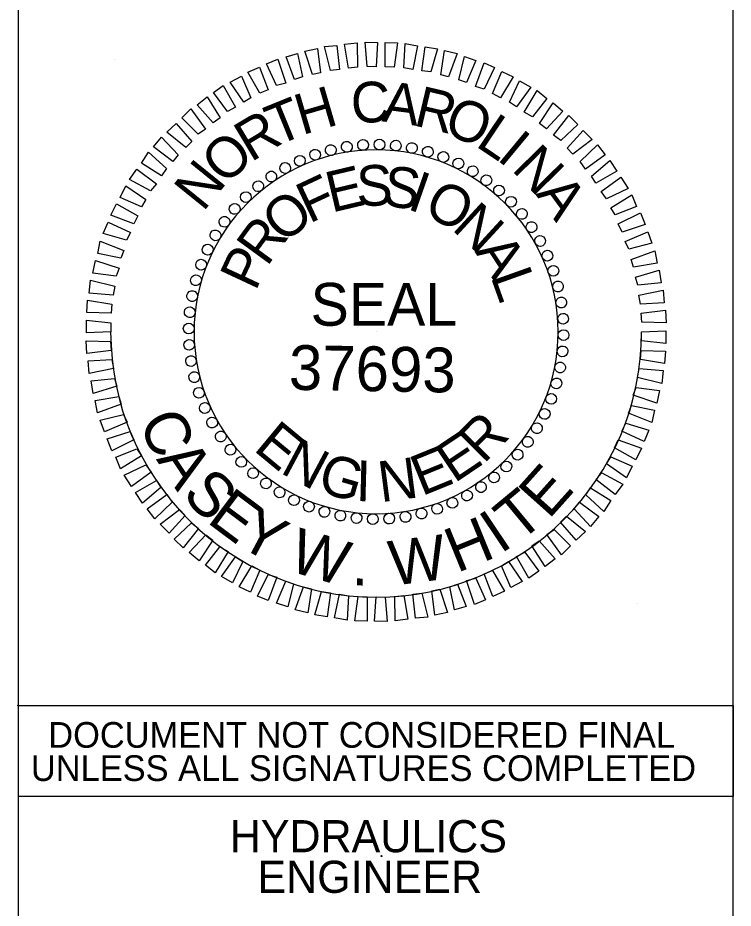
# Model space of a CAD drawing. Extents: x 2.6 to 3.27, y 0.03 to 1.77.
# Drawn here: x 2.604 to 2.7708, y 1.3512 to 1.5591 of the extents above; entities that cross this region are included whole.
import ezdxf

# ---------------------------------------------------------------- set-up
doc = ezdxf.new("R2010")
doc.units = 0
for name, color, linetype in [('Draft_RDY_Construction_Class_Element', 7, 'Continuous'), ('Scratch_Level_2', 7, 'Continuous'), ('Sheet_PE_Note_CELL', 7, 'Continuous'), ('Sheet_Plan_CELL', 7, 'Continuous'), ('Sheet_Sticker_Incomplete_CELL', 7, 'Continuous')]:
    doc.layers.add(name, color=color, linetype=linetype)

msp = doc.modelspace()

# ---------------------------------------------------------------- linework, layer by layer
at = {"layer": 'Draft_RDY_Construction_Class_Element'}
for p, q in [((2.60416, 0.0625), (2.60416, 1.77083)), ((2.77078, 1.77083), (2.77078, 0.0625))]:
    msp.add_line(p, q, dxfattribs=at)
at = {"layer": 'Scratch_Level_2'}
for p, q in [((2.62662, 1.54928), (2.62662, 1.54928)), ((2.68756, 1.48578), (2.68756, 1.48578)), ((2.7485, 1.42228), (2.7485, 1.42228))]:
    msp.add_line(p, q, dxfattribs=at)
for radius, start, end in [(0.04247, 0, 180), (0.06193, 180, 0), (0.04247, 180, 0)]:
    msp.add_arc((2.68756, 1.48578), radius, start, end, dxfattribs=at)
at = {"layer": 'Sheet_PE_Note_CELL'}
for p, q in [((2.67692, 1.52823), (2.67692, 1.52823)), ((2.68076, 1.52893), (2.68076, 1.52893)), ((2.68451, 1.52945), (2.68451, 1.52945)), ((2.68834, 1.52954), (2.68834, 1.52954)), ((2.69218, 1.52928), (2.69218, 1.52928)), ((2.69593, 1.52867), (2.69593, 1.52867)), ((2.67326, 1.52719), (2.67326, 1.52719)), ((2.69959, 1.52788), (2.69959, 1.52788)), ((2.70325, 1.52666), (2.70325, 1.52666)), ((2.66637, 1.52405), (2.66637, 1.52405)), ((2.66977, 1.52579), (2.66977, 1.52579)), ((2.70674, 1.52509), (2.70674, 1.52509)), ((2.66306, 1.52204), (2.66306, 1.52204)), ((2.71013, 1.52335), (2.71013, 1.52335)), ((2.66001, 1.51986), (2.66001, 1.51986)), ((2.71327, 1.52117), (2.71327, 1.52117)), ((2.71632, 1.51882), (2.71632, 1.51882)), ((2.65713, 1.51725), (2.65713, 1.51725)), ((2.71903, 1.5162), (2.71903, 1.5162)), ((2.65452, 1.51455), (2.65452, 1.51455)), ((2.65217, 1.51149), (2.65217, 1.51149)), ((2.72164, 1.51332), (2.72164, 1.51332)), ((2.72382, 1.51027), (2.72382, 1.51027)), ((2.64999, 1.50836), (2.64999, 1.50836)), ((2.72583, 1.50696), (2.72583, 1.50696)), ((2.64824, 1.50496), (2.64824, 1.50496)), ((2.72757, 1.50356), (2.72757, 1.50356)), ((2.64667, 1.50147), (2.64667, 1.50147)), ((2.72896, 1.50007), (2.72896, 1.50007)), ((2.64545, 1.49781), (2.64545, 1.49781)), ((2.73001, 1.49641), (2.73001, 1.49641)), ((2.64467, 1.49415), (2.64467, 1.49415)), ((2.73071, 1.49258), (2.73071, 1.49258)), ((2.64406, 1.4904), (2.64406, 1.4904)), ((2.73123, 1.48883), (2.73123, 1.48883)), ((2.6438, 1.48656), (2.6438, 1.48656)), ((2.73132, 1.48499), (2.73132, 1.48499)), ((2.64388, 1.48273), (2.64388, 1.48273)), ((2.73106, 1.48116), (2.73106, 1.48116)), ((2.64441, 1.47898), (2.64441, 1.47898)), ((2.73045, 1.47741), (2.73045, 1.47741)), ((2.6451, 1.47514), (2.6451, 1.47514)), ((2.72966, 1.47375), (2.72966, 1.47375)), ((2.64615, 1.47148), (2.64615, 1.47148)), ((2.72844, 1.47009), (2.72844, 1.47009)), ((2.64755, 1.468), (2.64755, 1.468)), ((2.72687, 1.4666), (2.72687, 1.4666)), ((2.64929, 1.4646), (2.64929, 1.4646)), ((2.72513, 1.4632), (2.72513, 1.4632)), ((2.65129, 1.46128), (2.65129, 1.46128)), ((2.72295, 1.46006), (2.72295, 1.46006)), ((2.65347, 1.45823), (2.65347, 1.45823)), ((2.65609, 1.45536), (2.65609, 1.45536)), ((2.7206, 1.45701), (2.7206, 1.45701)), ((2.71798, 1.45431), (2.71798, 1.45431)), ((2.65879, 1.45274), (2.65879, 1.45274)), ((2.7151, 1.45169), (2.7151, 1.45169)), ((2.66184, 1.45039), (2.66184, 1.45039)), ((2.71205, 1.44951), (2.71205, 1.44951)), ((2.66498, 1.44821), (2.66498, 1.44821)), ((2.70874, 1.44751), (2.70874, 1.44751)), ((2.66838, 1.44646), (2.66838, 1.44646)), ((2.67187, 1.44489), (2.67187, 1.44489)), ((2.70534, 1.44577), (2.70534, 1.44577)), ((2.67553, 1.44367), (2.67553, 1.44367)), ((2.67919, 1.44289), (2.67919, 1.44289)), ((2.69819, 1.44333), (2.69819, 1.44333)), ((2.70185, 1.44437), (2.70185, 1.44437)), ((2.68294, 1.44228), (2.68294, 1.44228)), ((2.68677, 1.44202), (2.68677, 1.44202)), ((2.69061, 1.44211), (2.69061, 1.44211)), ((2.69436, 1.44263), (2.69436, 1.44263))]:
    msp.add_line(p, q, dxfattribs=at)
for points in [[(2.68111, 1.54732), (2.68015, 1.5529), (2.68311, 1.55325), (2.6832, 1.54758)], [(2.68547, 1.54776), (2.68503, 1.55342), (2.68791, 1.55334), (2.68756, 1.54767)], [(2.68965, 1.54767), (2.68965, 1.55334), (2.69253, 1.55325), (2.69174, 1.54758)], [(2.69401, 1.54741), (2.69436, 1.55308), (2.69723, 1.55255), (2.6961, 1.54706)], [(2.67274, 1.54584), (2.67091, 1.55133), (2.67387, 1.55194), (2.67457, 1.54628)], [(2.67692, 1.5468), (2.67553, 1.55238), (2.6784, 1.55264), (2.67901, 1.54706)], [(2.69819, 1.54671), (2.69898, 1.55229), (2.70185, 1.55185), (2.70028, 1.54645)], [(2.70264, 1.54575), (2.70351, 1.55142), (2.70647, 1.55072), (2.70447, 1.54532)], [(2.66428, 1.54331), (2.66202, 1.54837), (2.66463, 1.54941), (2.66646, 1.54383)], [(2.66855, 1.54471), (2.66655, 1.54994), (2.66925, 1.55072), (2.67038, 1.54532)], [(2.70682, 1.54462), (2.70813, 1.55002), (2.71083, 1.54915), (2.70865, 1.54401)], [(2.66045, 1.54148), (2.65766, 1.54636), (2.66036, 1.54758), (2.66236, 1.54227)], [(2.71074, 1.54305), (2.71275, 1.54854), (2.71519, 1.5475), (2.71275, 1.54244)], [(2.6567, 1.53939), (2.65347, 1.5441), (2.65618, 1.54549), (2.65835, 1.54044)], [(2.71467, 1.54139), (2.71685, 1.54654), (2.71955, 1.54532), (2.71659, 1.54044)], [(2.65286, 1.53721), (2.64964, 1.54166), (2.6519, 1.54331), (2.65478, 1.53826)], [(2.71868, 1.53939), (2.72103, 1.54436), (2.72365, 1.54288), (2.72033, 1.53834)], [(2.64955, 1.53459), (2.6458, 1.53878), (2.64816, 1.54061), (2.65121, 1.53573)], [(2.72208, 1.53704), (2.72513, 1.54209), (2.72739, 1.54026), (2.724, 1.53599)], [(2.72565, 1.53442), (2.72888, 1.53921), (2.73114, 1.5373), (2.72731, 1.5332)], [(2.64606, 1.53189), (2.64223, 1.53573), (2.64432, 1.53782), (2.64772, 1.53311)], [(2.72896, 1.53172), (2.73254, 1.53625), (2.73463, 1.53416), (2.73062, 1.53041)], [(2.64319, 1.52884), (2.63874, 1.53242), (2.64092, 1.53442), (2.64458, 1.53024)], [(2.7321, 1.52867), (2.73585, 1.53276), (2.73794, 1.53067), (2.73341, 1.52727)], [(2.64014, 1.52553), (2.6356, 1.52893), (2.63752, 1.53119), (2.64136, 1.5271)], [(2.73515, 1.52553), (2.73916, 1.52945), (2.74099, 1.5271), (2.73637, 1.52379)], [(2.63752, 1.52222), (2.63281, 1.52518), (2.63447, 1.52771), (2.63865, 1.52387)], [(2.63491, 1.51873), (2.63002, 1.52134), (2.63177, 1.52379), (2.6363, 1.5203)], [(2.73777, 1.52213), (2.74204, 1.52579), (2.7437, 1.52326), (2.73881, 1.52047)], [(2.74003, 1.51856), (2.74465, 1.52187), (2.74631, 1.51925), (2.74126, 1.51681)], [(2.63281, 1.51498), (2.62784, 1.51716), (2.62915, 1.51986), (2.63386, 1.51664)], [(2.7423, 1.51472), (2.74718, 1.51777), (2.74832, 1.51507), (2.74335, 1.51306)], [(2.63107, 1.51097), (2.62567, 1.51298), (2.62697, 1.51568), (2.63194, 1.51289)], [(2.74404, 1.51097), (2.74919, 1.51359), (2.75032, 1.5108), (2.74492, 1.50905)], [(2.62933, 1.50714), (2.62392, 1.5087), (2.62505, 1.51141), (2.63029, 1.50897)], [(2.74561, 1.50687), (2.75093, 1.50914), (2.75189, 1.50644), (2.74649, 1.50504)], [(2.62802, 1.50295), (2.62261, 1.50408), (2.62322, 1.50696), (2.62872, 1.50478)], [(2.74701, 1.50269), (2.75259, 1.50469), (2.75311, 1.50182), (2.74762, 1.50086)], [(2.62689, 1.49877), (2.62148, 1.49946), (2.62209, 1.50243), (2.62758, 1.5006)], [(2.74805, 1.49851), (2.75355, 1.50016), (2.75407, 1.4972), (2.74858, 1.49667)], [(2.62619, 1.49432), (2.62061, 1.49484), (2.62096, 1.49781), (2.62662, 1.49641)], [(2.74884, 1.49432), (2.75451, 1.49554), (2.75477, 1.49258), (2.74919, 1.49223)], [(2.62575, 1.49014), (2.62009, 1.49031), (2.62026, 1.49319), (2.62593, 1.49223)], [(2.74936, 1.49014), (2.75503, 1.49083), (2.7552, 1.48787), (2.74954, 1.48804)], [(2.62567, 1.48578), (2.62, 1.48552), (2.62, 1.48848), (2.62567, 1.48787)], [(2.74945, 1.48578), (2.75512, 1.48604), (2.75512, 1.48308), (2.74945, 1.48369)], [(2.62575, 1.48142), (2.62009, 1.48072), (2.61991, 1.48369), (2.62558, 1.48351)], [(2.74936, 1.48142), (2.75503, 1.48125), (2.75485, 1.47837), (2.74919, 1.47933)], [(2.62628, 1.47724), (2.62061, 1.47602), (2.62035, 1.47898), (2.62593, 1.47933)], [(2.74893, 1.47724), (2.75451, 1.47671), (2.75416, 1.47375), (2.74849, 1.47514)], [(2.62706, 1.47305), (2.62157, 1.4714), (2.62105, 1.47436), (2.62654, 1.47488)], [(2.74823, 1.47279), (2.75363, 1.47209), (2.75302, 1.46913), (2.74753, 1.47096)], [(2.62811, 1.46887), (2.62253, 1.46686), (2.622, 1.46974), (2.6275, 1.4707)], [(2.7471, 1.46861), (2.7525, 1.46747), (2.75189, 1.4646), (2.7464, 1.46677)], [(2.6295, 1.46468), (2.62418, 1.46242), (2.62322, 1.46512), (2.62863, 1.46651)], [(2.74579, 1.46442), (2.75119, 1.46285), (2.75006, 1.46015), (2.74483, 1.46259)], [(2.63107, 1.46059), (2.62593, 1.45797), (2.62479, 1.46076), (2.6302, 1.4625)], [(2.74404, 1.46059), (2.74945, 1.45858), (2.74814, 1.45588), (2.74317, 1.45867)], [(2.63281, 1.45684), (2.62793, 1.45379), (2.6268, 1.45649), (2.63177, 1.45849)], [(2.7423, 1.45658), (2.74727, 1.4544), (2.74596, 1.45169), (2.74126, 1.45492)], [(2.63508, 1.453), (2.63046, 1.44969), (2.6288, 1.4523), (2.63386, 1.45475)], [(2.63735, 1.44943), (2.63307, 1.44577), (2.63142, 1.44829), (2.6363, 1.45108)], [(2.74021, 1.45283), (2.74509, 1.45021), (2.74335, 1.44777), (2.73881, 1.45126)], [(2.73759, 1.44934), (2.7423, 1.44638), (2.74064, 1.44385), (2.73646, 1.44768)], [(2.63996, 1.44603), (2.63595, 1.44211), (2.63412, 1.44446), (2.63874, 1.44777)], [(2.73498, 1.44603), (2.73951, 1.44263), (2.73759, 1.44036), (2.73376, 1.44446)], [(2.64301, 1.44289), (2.63926, 1.43879), (2.63717, 1.44088), (2.6417, 1.44428)], [(2.73193, 1.44272), (2.73637, 1.43914), (2.73419, 1.43714), (2.73053, 1.44132)], [(2.64615, 1.43984), (2.64258, 1.43531), (2.64048, 1.4374), (2.64449, 1.44115)], [(2.72905, 1.43966), (2.73289, 1.43583), (2.73079, 1.43374), (2.72739, 1.43844)], [(2.64946, 1.43714), (2.64624, 1.43234), (2.64397, 1.43426), (2.64781, 1.43836)], [(2.72556, 1.43696), (2.72931, 1.43278), (2.72696, 1.43095), (2.72391, 1.43583)], [(2.65304, 1.43452), (2.64999, 1.42947), (2.64772, 1.4313), (2.65112, 1.43557)], [(2.65644, 1.43217), (2.65408, 1.4272), (2.65147, 1.42868), (2.65478, 1.43321)], [(2.72225, 1.43435), (2.72548, 1.4299), (2.72321, 1.42824), (2.72033, 1.4333)], [(2.66045, 1.43016), (2.65827, 1.42502), (2.65557, 1.42624), (2.65853, 1.43112)], [(2.71842, 1.43217), (2.72164, 1.42746), (2.71894, 1.42607), (2.71676, 1.43112)], [(2.66437, 1.42851), (2.66236, 1.42301), (2.65992, 1.42406), (2.66236, 1.42912)], [(2.71083, 1.42824), (2.7131, 1.42319), (2.71048, 1.42214), (2.70865, 1.42772)], [(2.71467, 1.43008), (2.71746, 1.42519), (2.71475, 1.42397), (2.71275, 1.42929)], [(2.66829, 1.42694), (2.66698, 1.42153), (2.66428, 1.4224), (2.66646, 1.42755)], [(2.67248, 1.4258), (2.6716, 1.42014), (2.66864, 1.42084), (2.67065, 1.42624)], [(2.70656, 1.42685), (2.70857, 1.42162), (2.70586, 1.42084), (2.70473, 1.42624)], [(2.67692, 1.42485), (2.67614, 1.41927), (2.67326, 1.4197), (2.67483, 1.42511)], [(2.68111, 1.42415), (2.68076, 1.41848), (2.67788, 1.419), (2.67901, 1.4245)], [(2.69401, 1.42424), (2.69497, 1.41866), (2.692, 1.41831), (2.69192, 1.42397)], [(2.69819, 1.42476), (2.69959, 1.41918), (2.69671, 1.41892), (2.6961, 1.4245)], [(2.70238, 1.42572), (2.70421, 1.42023), (2.70124, 1.41961), (2.70055, 1.42528)], [(2.68547, 1.42389), (2.68547, 1.41822), (2.68259, 1.41831), (2.68337, 1.42397)], [(2.68965, 1.4238), (2.69009, 1.41813), (2.68721, 1.41822), (2.68756, 1.42389)]]:
    msp.add_lwpolyline(points, close=True, dxfattribs=at)
for centre, major_axis in [((2.68072, 1.52897), (-0.0002, 0.00124)), ((2.68451, 1.5294), (-0.00009, 0.00125)), ((2.68832, 1.5295), (0.00002, 0.00126)), ((2.69213, 1.52926), (0.00013, 0.00125)), ((2.6959, 1.5287), (0.00024, 0.00123)), ((2.67332, 1.52712), (-0.00041, 0.00119)), ((2.67698, 1.5282), (-0.0003, 0.00122)), ((2.69961, 1.52781), (0.00035, 0.00121)), ((2.70323, 1.5266), (0.00045, 0.00117)), ((2.66977, 1.52572), (-0.00051, 0.00115)), ((2.70673, 1.52508), (0.00055, 0.00113)), ((2.66636, 1.52402), (-0.00061, 0.0011)), ((2.71008, 1.52326), (0.00065, 0.00108)), ((2.66311, 1.52203), (-0.0007, 0.00104)), ((2.71326, 1.52115), (0.00074, 0.00102)), ((2.66004, 1.51976), (-0.00079, 0.000976)), ((2.71624, 1.51878), (0.000824, 0.000947)), ((2.65718, 1.51723), (-0.000872, 0.000903)), ((2.71901, 1.51615), (0.000903, 0.000872)), ((2.65456, 1.51446), (-0.000947, 0.000824)), ((2.72154, 1.5133), (0.000976, 0.00079)), ((2.65218, 1.51148), (-0.00102, 0.00074)), ((2.72381, 1.51023), (0.00104, 0.0007)), ((2.65008, 1.5083), (-0.00108, 0.00065)), ((2.7258, 1.50698), (0.0011, 0.00061)), ((2.64826, 1.50495), (-0.00113, 0.00055)), ((2.7275, 1.50356), (0.00115, 0.00051)), ((2.64674, 1.50145), (-0.00117, 0.00045)), ((2.7289, 1.50001), (0.00119, 0.00041)), ((2.64553, 1.49783), (-0.00121, 0.00035)), ((2.72998, 1.49636), (0.00122, 0.0003)), ((2.64464, 1.49412), (-0.00123, 0.00024)), ((2.73074, 1.49262), (0.00124, 0.0002)), ((2.64407, 1.49035), (-0.00125, 0.00013)), ((2.73118, 1.48883), (0.00125, 0.00009)), ((2.64384, 1.48654), (-0.00126, 0.00002)), ((2.73128, 1.48502), (0.00126, -0.00002)), ((2.64394, 1.48273), (-0.00125, -0.00009)), ((2.73104, 1.48121), (0.00125, -0.00013)), ((2.64437, 1.47894), (-0.00124, -0.0002)), ((2.73048, 1.47744), (0.00123, -0.00024)), ((2.64513, 1.4752), (-0.00122, -0.0003)), ((2.72959, 1.47373), (0.00121, -0.00035)), ((2.64621, 1.47154), (-0.00119, -0.00041)), ((2.72838, 1.47011), (0.00117, -0.00045)), ((2.64761, 1.46799), (-0.00115, -0.00051)), ((2.72686, 1.46661), (0.00113, -0.00055)), ((2.64931, 1.46458), (-0.0011, -0.00061)), ((2.72504, 1.46326), (0.00108, -0.00065)), ((2.65131, 1.46133), (-0.00104, -0.0007)), ((2.72293, 1.46008), (0.00102, -0.00074)), ((2.65358, 1.45826), (-0.000976, -0.00079)), ((2.72056, 1.45709), (0.000947, -0.000824)), ((2.6561, 1.4554), (-0.000903, -0.000872)), ((2.71793, 1.45432), (0.000872, -0.000903)), ((2.65887, 1.45278), (-0.000824, -0.000947)), ((2.71507, 1.4518), (0.00079, -0.000976)), ((2.66186, 1.4504), (-0.00074, -0.00102)), ((2.66504, 1.4483), (-0.00065, -0.00108)), ((2.70876, 1.44754), (0.00061, -0.0011)), ((2.71201, 1.44953), (0.0007, -0.00104)), ((2.66839, 1.44648), (-0.00055, -0.00113)), ((2.70534, 1.44583), (0.00051, -0.00115)), ((2.67189, 1.44496), (-0.00045, -0.00117)), ((2.6755, 1.44375), (-0.00035, -0.00121)), ((2.70179, 1.44444), (0.00041, -0.00119)), ((2.67921, 1.44286), (-0.00024, -0.00123)), ((2.68299, 1.44229), (-0.00013, -0.00125)), ((2.68679, 1.44206), (-0.00002, -0.00126)), ((2.69061, 1.44216), (0.00009, -0.00125)), ((2.6944, 1.44259), (0.0002, -0.00124)), ((2.69814, 1.44335), (0.0003, -0.00122))]:
    msp.add_ellipse(centre, major_axis=major_axis, ratio=0.999708, dxfattribs=at)
at = {"layer": 'Sheet_Plan_CELL'}
msp.add_line((2.77084, 1.37732), (2.60417, 1.37732), dxfattribs=at)
for centre in [(2.68745, 1.4923), (2.60407, 1.39855), (2.68878, 1.36338)]:
    msp.add_circle(centre, 0.0001, dxfattribs=at)
at = {"layer": 'Sheet_Sticker_Incomplete_CELL'}
msp.add_lwpolyline([(2.60417, 1.39855), (2.77084, 1.39855), (2.77084, 1.37732), (2.60417, 1.37732)], close=True, dxfattribs=at)

# ---------------------------------------------------------------- texts
at = {"layer": 'Sheet_PE_Note_CELL'}
for s, height, rotation, p in [('H', 0.0095, 16.2881, (2.67028, 1.53167)), ('C', 0.0095, 1.4832, (2.68176, 1.53454)), ('A', 0.0095, 352.5864, (2.68873, 1.53494)), ('R', 0.0095, 346.666, (2.69605, 1.53402)), ('T', 0.0095, 22.179, (2.66429, 1.5291)), ('O', 0.0095, 337.821, (2.70288, 1.53234)), ('R', 0.0095, 30.9582, (2.65834, 1.52528)), ('L', 0.0095, 326.1343, (2.71049, 1.52928)), ('I', 0.0095, 320.353, (2.71547, 1.52615)), ('O', 0.0095, 42.5191, (2.65228, 1.51978)), ('N', 0.0095, 314.6222, (2.71894, 1.5236)), ('N', 0.0095, 51.0517, (2.64718, 1.51361)), ('E', 0.0095, 13.334, (2.67715, 1.51357)), ('S', 0.0095, 1.4832, (2.68303, 1.51511)), ('S', 0.0095, 352.5864, (2.68881, 1.5153)), ('F', 0.0095, 25.1139, (2.67196, 1.51098)), ('I', 0.0095, 340.7633, (2.69454, 1.51452)), ('O', 0.0095, 331.9594, (2.69823, 1.51345)), ('A', 0.0095, 306.1346, (2.72462, 1.51794)), ('O', 0.0095, 39.647, (2.66597, 1.50612)), ('N', 0.0095, 317.4809, (2.70499, 1.50974)), ('R', 0.0095, 53.8654, (2.66207, 1.5008)), ('P', 0.0095, 64.9491, (2.6594, 1.49507)), ('A', 0.0095, 303.3373, (2.71045, 1.50454)), ('L', 0.0095, 289.6205, (2.7142, 1.49873)), ('37693', 0.010461, 359, (2.66714, 1.47226)), ('C', 0.01046, 295.0509, (2.63198, 1.46464)), ('R', 0.0095, 45.3778, (2.71262, 1.45479)), ('E', 0.0095, 320.353, (2.6587, 1.45825)), ('E', 0.0095, 33.8657, (2.70579, 1.45032)), ('N', 0.0095, 331.9594, (2.66492, 1.45296)), ('A', 0.01046, 303.3373, (2.63615, 1.45602)), ('E', 0.0095, 22.179, (2.69819, 1.44734)), ('G', 0.0095, 343.7119, (2.67351, 1.44862)), ('I', 0.0095, 358.5168, (2.68271, 1.44628)), ('N', 0.0095, 7.4136, (2.68863, 1.44598)), ('S', 0.01046, 314.6222, (2.64201, 1.44751)), ('E', 0.01046, 48.2222, (2.7278, 1.44181)), ('E', 0.01046, 323.2378, (2.64781, 1.44145)), ('T', 0.01046, 39.647, (2.72084, 1.43634)), ('Y', 0.01046, 331.9594, (2.65481, 1.43603)), ('I', 0.01046, 33.8657, (2.71655, 1.43382)), ('H', 0.01046, 22.179, (2.7064, 1.42942)), ('W', 0.01046, 343.7119, (2.66675, 1.43008)), ('W', 0.01046, 7.4136, (2.69126, 1.42646)), ('.', 0.01046, 358.5168, (2.68179, 1.42661))]:
    msp.add_text(s, height=height, rotation=rotation, dxfattribs=at).set_placement(p)
msp.add_text('SEAL', height=0.01, dxfattribs=at).set_placement((2.67227, 1.4872))
at = {"layer": 'Sheet_Plan_CELL'}
for s, p in [('HYDRAULICS', (2.65342, 1.36427)), ('ENGINEER', (2.65988, 1.35479))]:
    msp.add_text(s, height=0.0075, rotation=0, dxfattribs=at).set_placement(p)
at = {"layer": 'Sheet_Sticker_Incomplete_CELL'}
for s, p in [('DOCUMENT NOT CONSIDERED FINAL', (2.61108, 1.38867)), ('UNLESS ALL SIGNATURES COMPLETED', (2.60703, 1.38091))]:
    msp.add_text(s, height=0.006, rotation=0, dxfattribs=at).set_placement(p)

doc.saveas('drawing.dxf')
